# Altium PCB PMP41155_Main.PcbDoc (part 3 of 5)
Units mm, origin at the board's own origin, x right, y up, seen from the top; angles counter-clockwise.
Board outline 74 x 146.5 mm, 8 copper layers (Top Layer, Signal Layer 1, Signal Layer 2, Signal Layer 3, Signal Layer 4, Signal Layer 5, Signal Layer 6, Bottom Layer), stack 1.534 mm thick; 249 components, 190 nets, 902 pads, 747 vias.
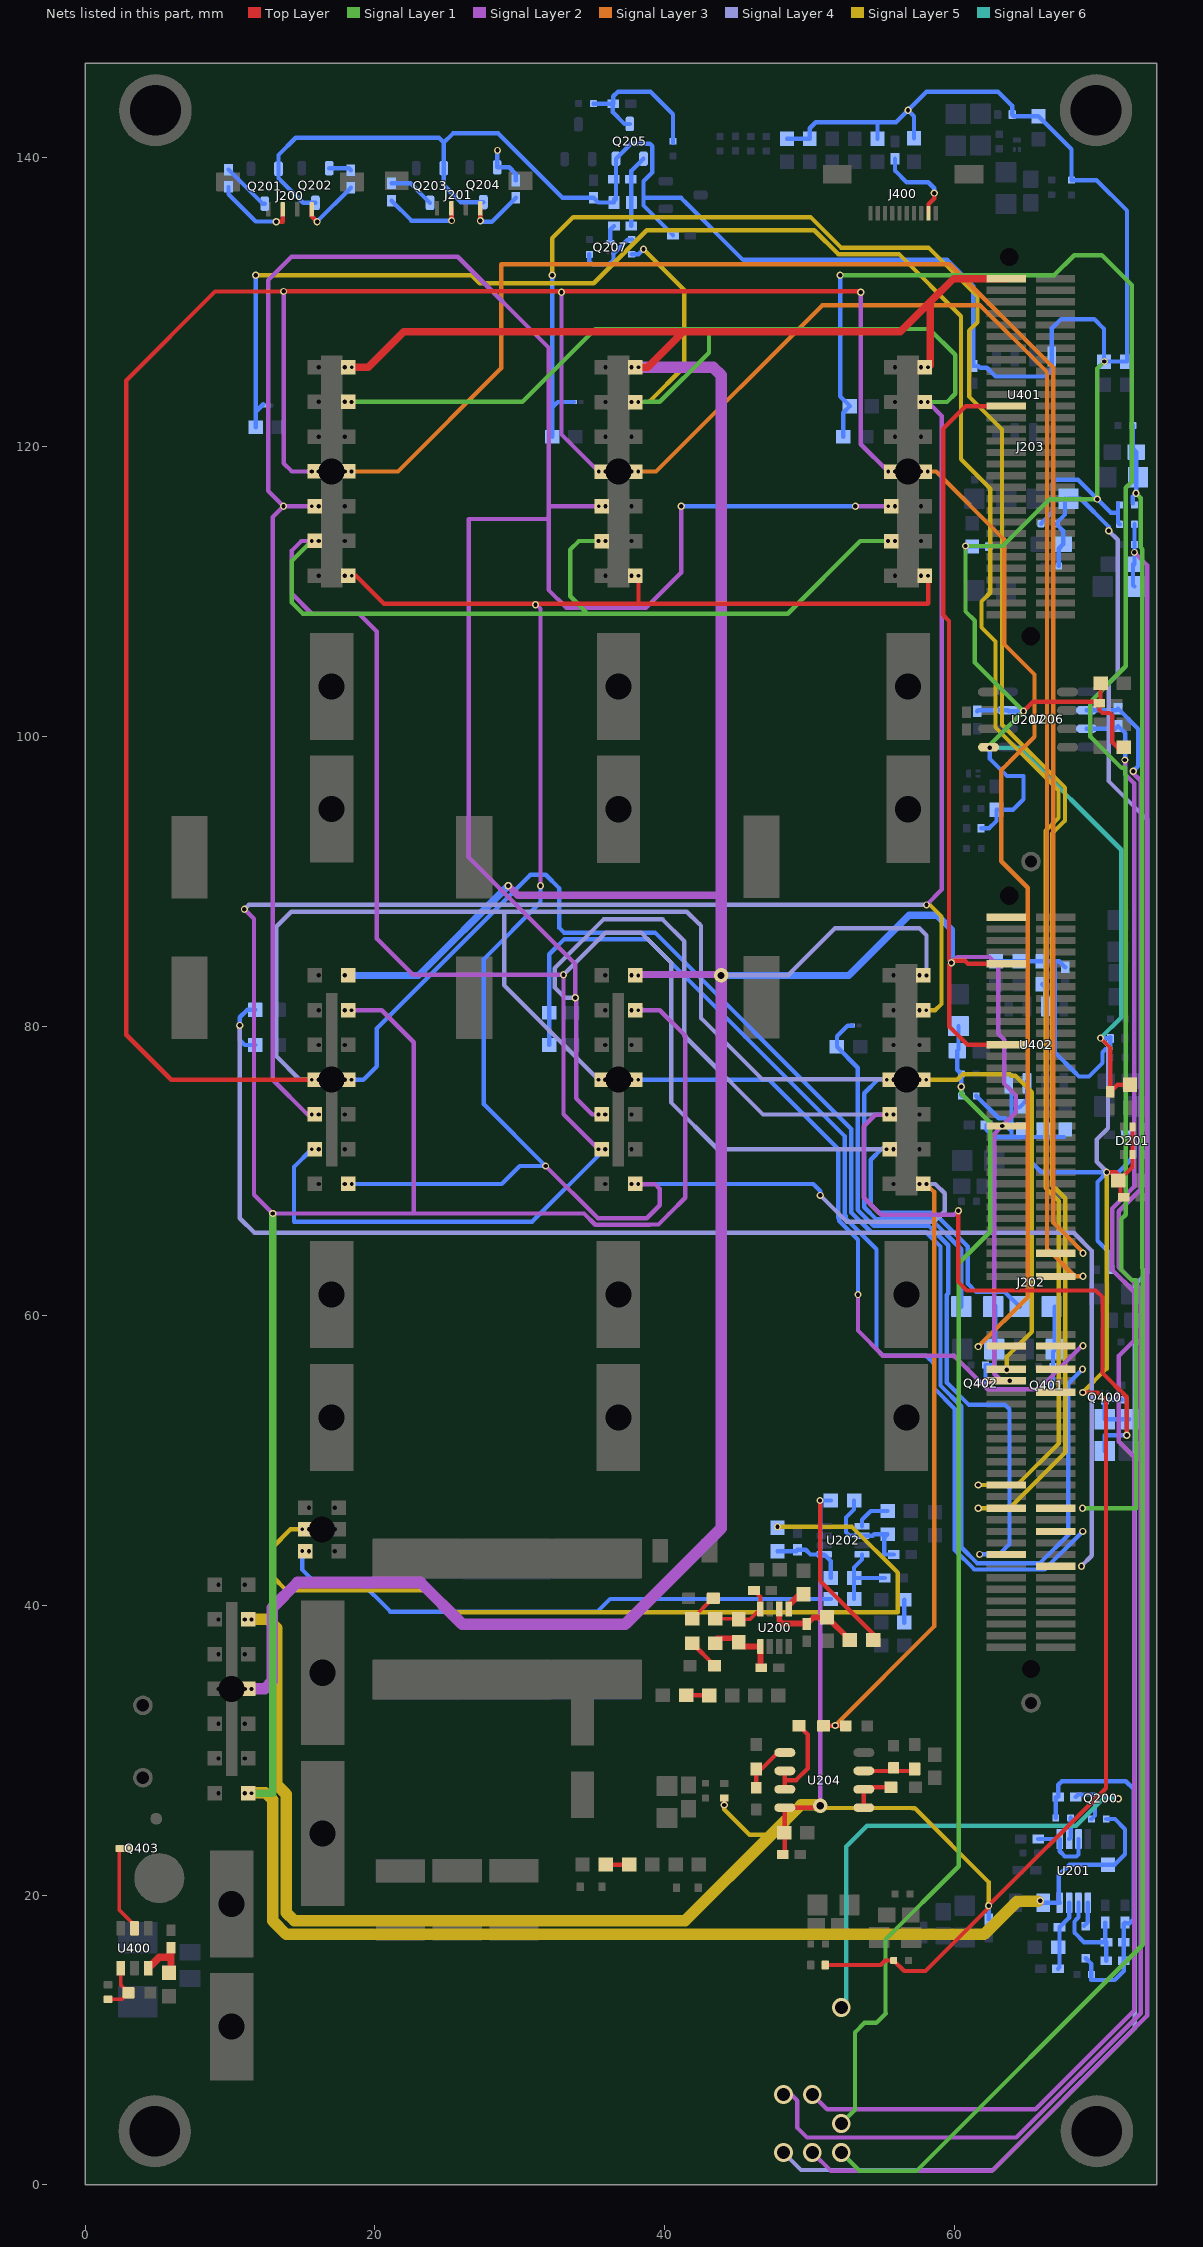
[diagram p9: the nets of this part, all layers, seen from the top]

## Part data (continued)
R243: library part CMP-0031931-1, "0 Ohms Jumper Chip Resistor 0603 (1608 Metric) Metal Element", Digikey Part Number=541-3927-1-ND, Manufacturer=Vishay, Mouser Part Number=71-WSL060300000ZEA9, Operating Temperature Range="-65°C to +170°C", TempCo=3900ppm/°C
R244: library part CMP-0026408-2, "RES, 4.32 k, 1%, 0.063 W, AEC-Q200 Grade 0, 0402", Manufacturer=Vishay-Dale, Power_W=63mW, Supplier Part Number 1=541-4.32KLCT-ND, TempCo="100 ppm/C", Tolerance_%=1%, Value2=0.063W, Value_Code=4k32, ValueDisplayed=4.32k
R249 R255: library part CMP-0026918-5, "RES, 3.3 k, 5%, 0.063 W, AEC-Q200 Grade 0, 0402", Manufacturer=Vishay-Dale, Power_W=63mW, Supplier Part Number 1=541-3.3KJCT-ND, TempCo="200 ppm/C", Tolerance_%=5%, Value2=0.063W, Value_Code=3k30, ValueDisplayed=3.3k
R250 R258 R265 R408 R422 R437 R451: library part CMP-0094182-1, "100 kOhms ±5% 0.063W, 1/16W Chip Resistor 0402 (1005 Metric) Moisture Resistant Thick Film", Digikey Part Number=311-100KJRCT-ND, Manufacturer=YAGEO, Mouser Part Number=603-RC0402JR-07100KL, Operating Temperature Range="-55°C to +155°C", Power_W=63mW, TempCo=100ppm/°C, Tolerance_%=5%
R251 R252 R254 R259 R262 R263 R266 R412 R413 R428 R429 R433 R434 R435 R436 R446 R447 R448 R449: library part CMP-0023152-5, "RES, 4.75 k, 1%, 0.1 W, 0603", Manufacturer=Yageo, Power_W=100mW, Supplier Part Number 1=311-4.75KHRCT-ND, TempCo="100 ppm/C", Tolerance_%=1%, Value2=0.1W, Value_Code=4k75, ValueDisplayed=4.75k
R253 R256: library part CMP-0121543-1, "0 Ohms Jumper Chip Resistor 0402 (1005 Metric) Automotive AEC-Q200 Thick Film", Digikey Part Number=10-ERJ-H2G0R00XCT-ND, Manufacturer=Panasonic, Mouser Part Number=667-ERJ-H2G0R00X, Operating Temperature Range="-55°C to +175°C"
R257 R264: library part CMP-0026833-3, "RES, 120, 5%, 0.063 W, AEC-Q200 Grade 0, 0402", Manufacturer=Vishay-Dale, Power_W=63mW, Supplier Part Number 1=541-120JCT-ND, TempCo="200 ppm/C", Tolerance_%=5%, Value2=0.063W, Value_Code=120R, ValueDisplayed=120
R260 R261 R268 R269 R400 R401 R402 R403 R404 R405 R414 R415 R416 R417 R425 R426 R427 R440 R441 R442 R453 R454 R455: library part CMP-0096818-1, "0 Ohms Jumper 0.245W Chip Resistor 0805 (2012 Metric) - Metal Element", Digikey Part Number=JR0805X35ECT-ND, Manufacturer=Ohmite, Mouser Part Number=588-JR0805X35E, Operating Temperature Range="-55°C to +150°C", Power_W=245mW
R267: library part CMP-0022745-5, "RES, 10.7 k, 1%, 0.1 W, 0603", Manufacturer=Yageo, Power_W=100mW, Supplier Part Number 1=311-10.7KHRCT-ND, TempCo="100 ppm/C", Tolerance_%=1%, Value2=0.1W, Value_Code=10k7, ValueDisplayed=10.7k
R300 R301 R302 R303 R304 R305: library part CMP-0096319-1, "400 µOhms ±1% 9W Chip Resistor Nonstandard Automotive AEC-Q200, Current Sense, Moisture Resistant Metal Element", Digikey Part Number=YAG6132CT-ND, Manufacturer=YAGEO, Mouser Part Number=603-PU3921FKNP90U4L, Operating Temperature Range="-65°C to +170°C", Power_W=9W, TempCo=175ppm/°C, Tolerance_%=1%
R406: library part CMP-0094733-1, "100Ω ±1% 0.063W 0402 Thick Film Chip Resistor AEC-Q200 compliant", Manufacturer="Stackpole Electronics", Operating Temperature Range="-55°C to +155°C", Power_W=63mW, TempCo=100ppm/°C, Tolerance_%=1%
R407: library part CMP-0026716-1, "RES, 1.00 k, 1%, 0.063 W, 0402", Manufacturer=Rohm, Power_W=63mW, Supplier Part Number 1=RHM1.00KLCT-ND, TempCo="100 ppm/C", Tolerance_%=1%, Value2=0.063W, Value_Code=1k00, ValueDisplayed=1.00k
R411 R438 R450: library part CMP-0026996-2, "RES, 20 k, 5%, 0.1 W, AEC-Q200 Grade 0, 0402", Manufacturer=Panasonic, Power_W=100mW, Supplier Part Number 1=P20KJCT-ND, TempCo="200 ppm/C", Tolerance_%=5%, Value2=0.1W, Value_Code=20k0, ValueDisplayed=20k
RT400: library part CMP-0002562-3, "Thermistor NTC, 50 ohm, 25%, D12.5xH16.5mm", Manufacturer=TDK, Supplier Part Number 1=495-3880-ND, Tolerance_%=25%
U200: library part CMP-0093655-2, "-4-V to 110-V, Bidirectional, 1-MHz, 5V/μs, Ultra-Precise Current Sense Amplifier, SOT23-8", Input Bias Current=40uA, Input Offset Voltage=0.002mV, Manufacturer="Texas Instruments", Max Supply Voltage=20V, Min Supply Voltage=2.7V, Nominal Supply Current=2.5mA, Operating Temperature Range="-40°C to +125°C", Voltage Gain=0.1V/mV
U201: library part CMP-0124506-1, "Automotive, High-Voltage, Precision, Rail-to-Rail In, Rail-to-Rail Out Op Amp", Input Bias Current=5pA, Input Offset Voltage=5uV, Manufacturer="Texas Instruments", Max Dual Supply Voltage=18V, Max Supply Voltage=36V, Min Dual Supply Voltage=2.25V, Min Supply Voltage=4.5V, Nominal Supply Current=1mA, Operating Temperature Range="-40°C to +125°C", Output Current Per Channel=65mA, Voltage Gain=140dB
U202: library part CMP-0093654-2, "-4-V to 110-V, Bidirectional, 1-MHz, 5V/μs, Ultra-Precise Current Sense Amplifier, SOT23-8", Input Bias Current=40uA, Input Offset Voltage=0.002mV, Manufacturer="Texas Instruments", Max Supply Voltage=20V, Min Supply Voltage=2.7V, Nominal Supply Current=2.5mA, Operating Temperature Range="-40°C to +125°C", Voltage Gain=0.05V/mV
U204: library part CMP-0013007-4, "10-MHz, Low-Noise, RRIO, CMOS Operational Amplifier for Cost-Sensitive Systems, D0008A (SOIC-8)", Alternate Manufacturer="Texas Instruments", Alternate PartNumber=TLV9062ID, Operating Temperature Range="-40 to 125 C", Rating=Catalog
U206: library part CMP-0033354-1, "3.3V CAN Transceiver with Sleep Mode, 6 mA, -40 to 125 degC, 8-pin SOIC (D), Green (RoHS & no Sb/Br)", Bus Fault Voltage(V)=+/-30, Drivers Per Package=1, Low Power Mode=Sleep, Manufacturer="Texas Instruments", Rating=Catalog, Supply Voltage(s)(V)=3.3
U207: library part CMP-0029827-1, "3.3 V Supply RS-485 with IEC ESD Protection, 20 Mbps, -40 to 125 degC, 8-Pin SOIC, RoHS, Tape and Reel", Manufacturer="Texas Instruments", Operating Temperature Range="-40 to 125 degC"
U400: library part CMP-0066129-2, "High Side OR-ing FET Controller, DDC0006A (SOT-23-T-6)", Alternate Manufacturer="Texas Instruments"
U401 U402: library part CMP-0086585-1, "IC EEPROM 1M I2C 1MHZ 8SO", Manufacturer="ST Microelectronics"

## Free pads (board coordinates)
  round 5 hole 3.5: 1(4.8,3.7) 1(4.85,143.25) 1(69.8,143.25) 1(69.86,3.7)
  rect 1x1 hole 0.3 copper offset -0.254,0: 1(9.21,27.04) 1(9.21,29.44) 1(9.21,31.84) 1(9.21,34.24) 1(9.21,36.64) 1(9.21,39.04) 1(9.21,41.44) 1(15.46,45.26) 1(15.46,46.76) 1(15.46,43.76) 1(16.12,69.11) 1(16.12,71.51) 1(16.12,73.91) 1(16.12,76.31) 1(16.12,78.71) 1(16.12,81.11) 1(16.12,83.51) 1(16.12,111.11) 1(16.12,113.51) 1(16.12,115.91) 1(16.12,118.31) 1(16.12,120.71) 1(16.12,123.11) 1(16.12,125.51) 1(35.92,69.11) 1(35.92,71.51) 1(35.92,73.91) 1(35.92,76.31) 1(35.92,78.71) 1(35.92,81.11) 1(35.92,83.51) 1(35.924,111.103) 1(35.924,113.503) 1(35.924,115.903) 1(35.924,118.303) 1(35.924,120.703) 1(35.924,123.103) 1(35.924,125.503) 1(55.81,69.11) 1(55.81,71.51) 1(55.81,73.91) 1(55.81,76.31) 1(55.81,78.71) 1(55.81,81.11) 1(55.81,83.51) 1(55.918,111.105) 1(55.918,113.505) 1(55.918,115.905) 1(55.918,118.305) 1(55.918,120.705) 1(55.918,123.105) 1(55.918,125.505)
  rect 1x1 hole 0.3 copper offset 0.254,0: 1(11.01,27.04) 1(11.01,29.44) 1(11.01,31.84) 1(11.01,34.24) 1(11.01,36.64) 1(11.01,39.04) 1(11.01,41.44) 1(17.24,46.76) 1(17.24,43.76) 1(17.24,45.26) 1(17.92,69.11) 1(17.92,71.51) 1(17.92,73.91) 1(17.92,76.31) 1(17.92,78.71) 1(17.92,81.11) 1(17.92,83.51) 1(17.92,111.11) 1(17.92,113.51) 1(17.92,115.91) 1(17.92,118.31) 1(17.92,120.71) 1(17.92,123.11) 1(17.92,125.51) 1(37.72,69.11) 1(37.72,71.51) 1(37.72,73.91) 1(37.72,76.31) 1(37.72,78.71) 1(37.72,81.11) 1(37.72,83.51) 1(37.724,111.103) 1(37.724,113.503) 1(37.724,115.903) 1(37.724,118.303) 1(37.724,120.703) 1(37.724,123.103) 1(37.724,125.503) 1(57.61,69.11) 1(57.61,71.51) 1(57.61,73.91) 1(57.61,76.31) 1(57.61,78.71) 1(57.61,81.11) 1(57.61,83.51) 1(57.718,111.105) 1(57.718,113.505) 1(57.718,115.905) 1(57.718,118.305) 1(57.718,120.705) 1(57.718,123.105) 1(57.718,125.505)
  rect 3x7.4 hole 1.8 square: 2(10.11,10.92) 2(17.02,52.99) 2(17.02,94.99) 2(36.82,52.99) 2(36.824,94.983) 2(56.71,52.99) 2(56.818,94.985)
  rect 3x7.4 hole 1.8 square unplated: 2(10.11,19.4) 2(17.02,61.47) 2(17.02,103.47) 2(36.82,61.47) 2(36.824,103.463) 2(56.71,61.47) 2(56.818,103.465)
  rect 0.8x12 hole 1.8 square unplated: 2(10.11,34.24) 2(17.02,76.31) 2(36.82,76.31)
  rect 0.8x1.6 hole 1.8 square unplated: 2(16.35,45.26)
  rect 3x10 hole 1.8 square: 2(16.4,24.25) 2(16.4,35.36)
  rect 1.5x16 hole 1.8 square: 2(17.02,118.31) 2(36.824,118.303) 2(56.71,76.31) 2(56.818,118.305)

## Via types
v1: diameter 0.5, hole 0.3, Top Layer to Bottom Layer, 533 vias
v2: diameter 0.508, hole 0.254, Top Layer to Bottom Layer, tented both sides, 102 vias
v3: diameter 1.5, hole 1.2, Top Layer to Bottom Layer, 72 vias
v4: diameter 1.3, hole 0.9, Top Layer to Bottom Layer, 30 vias
v5: diameter 1.27, hole 0.711, Top Layer to Bottom Layer, 6 vias
v6: diameter 1, hole 0.5, Top Layer to Bottom Layer, 2 vias
v7: diameter 2.49, hole 2.49, Top Layer to Bottom Layer, 2 vias

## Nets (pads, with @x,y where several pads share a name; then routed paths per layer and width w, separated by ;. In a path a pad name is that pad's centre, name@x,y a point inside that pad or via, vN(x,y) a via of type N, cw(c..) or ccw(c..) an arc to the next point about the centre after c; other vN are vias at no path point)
3V3: C217.1 C218.1 C222.2 C231.1 C233.1 C406.1 C411.1 D201.2 D201.5 J202.45 pad.1@11.01,39.04 Q201.2 Q202.3 Q203.2 Q204.3 Q205.2 R203.1 R210.1 R236.2 R241.2 R248.2 R249.1 R250.2 R251.2 R252.2 R254.2 R255.1 R258.2 R259.2 R262.2 R263.2 R265.2 R266.2 R408.2 R409.2 R410.2 R411.2 R412.2 R413.2 R422.2 R423.2 R424.2 R428.2 R429.2 R433.2 R434.2 R435.2 R436.2 R437.2 R438.2 R439.2 R446.2 R447.2 R448.2 R449.2 R450.2 R451.2 R452.2 U204.8 U206.3 U207.8 U401.8 U402.8 | length 504.7
  Top Layer w0.3: v1(44.13,26.23) 44.13,26.699 R422.2@44.139,26.708 ; C218.1@48.17,22.804 48.315,22.949 C217.1@48.315,24.314 ; C217.1@48.26,24.314 C217.1@48.26,24.569 ; C217.1@48.315,24.569 U204.8@48.315,26.039 50.621,26.039 v6(50.764,26.182) ; v1(50.738,47.253) 50.738,41.712 54.41,38.04 R203.1@54.41,37.615 ; R408.2@51.101,15.181 54.941,15.181 55.251,15.491 R452.2@55.823,15.491 56.554,14.76 58.025,14.76 62.381,19.117 v1(62.381,19.278) 70.483,27.38 70.483,54.134 69.907,54.71 v1(68.88,54.71) ; v1(64.79,101.75) 65.444,102.404 69.926,102.404 C233.1@70.03,102.3 ; v1(70.11,79.18) 70.791,78.499 R255.1@70.791,75.468 71.283,75.96 R254.2@72.14,75.96 ; R262.2@70.11,103.69 70.11,102.38 C233.1@70.03,102.3 ; v1(70.53,69.92) 71.175,69.92 71.33,69.765 R252.2@71.33,69.34 71.487,69.183 71.487,68.423 R249.1@71.72,68.19 ; R252.2@71.38,69.34 72.32,70.28 D201.5@72.32,71.14 D201.2@72.32,73.04 ; R263.2@71.722,99.257 71.283,99.257 70.922,99.618 70.922,100.948 70.919,100.951 70.919,101.455 70.745,101.629 70.241,101.629 70.03,101.84 C233.1@70.03,102.3
  Signal Layer 2 w0.3: v1(50.738,47.253) 50.764,47.227 v6(50.764,26.182)
  Signal Layer 1 w0.3: v1(62.473,99.218) 62.473,99.433 v1(64.79,101.75) 61.419,105.121 61.419,108.011 60.784,108.646 v1(60.784,113.159) 63.364,113.159 66.605,116.4 v1(69.89,116.4) 69.89,125.413 v1(70.377,125.9)
  Signal Layer 4 w0.3: v1(70.11,79.18) 70.622,78.668 70.622,72.955 69.849,72.183 69.849,70.651 v1@70.58,69.92
  Signal Layer 5 w0.3: v1(44.13,26.23) 44.13,25.914 45.874,24.17 47.366,24.17 ; v6(50.764,26.182) 50.927,26.02 57.106,26.02 57.113,26.013 57.279,26.013 62.381,20.91 v1(62.381,19.278) ; v1(68.88,54.71) 70.53,56.36 v1(70.53,69.92)
  Signal Layer 5 w0.8: pad.1@11.566,39.04 12.65,39.04 13.24,38.45 13.24,27.624 13.887,26.977 13.887,18.794 14.434,18.247 41.443,18.247 47.366,24.17 49.426,26.23 50.764,26.23 v6(50.764,26.182)
  Signal Layer 6 w0.3: v1(62.473,99.218) 64.512,99.218 71.54,92.19 71.54,80.61 v1(70.11,79.18)
  Bottom Layer w0.3: Q202.3@15.9,136.855 15.053,136.855 13.347,138.561 Q201.2@13.347,139.201 13.347,140.157 14.54,141.35 24.434,141.35 24.763,141.021 ; Q204.3@27.498,136.908 25.932,136.908 24.763,138.077 Q203.2@24.763,139.253 24.763,141.021 ; C222.2@36.517,137.097 C222.2@36.517,136.877 35.435,136.877 R241.2@35.1,137.212 32.958,137.212 28.518,141.652 25.395,141.652 24.763,141.021 ; C222.2@36.652,137.097 Q205.2@36.652,139.902 37.687,140.938 38.985,140.938 39.149,140.773 39.149,138.948 38.552,138.351 38.552,137.198 ; R248.2@40.59,134.63 38.552,136.668 38.552,137.198 ; R446.2@48.465,141.28 R447.2@50.025,141.28 50.025,142.003 50.442,142.42 54.705,142.42 ; v1(50.738,47.253) R210.1@51.488,47.253 ; R448.2@54.705,141.29 54.705,142.42 ; R449.2@57.23,141.31 57.23,142.838 v1(56.818,143.25) ; v1(60.784,113.159) 60.816,113.126 R259.2@61.259,113.126 R258.2@62.575,113.126 ; R410.2@61.533,75.19 63.078,73.644 63.089,73.654 63.542,73.654 63.863,73.334 63.863,72.88 63.852,72.87 63.968,72.755 ; C231.1@61.59,101.755 61.655,101.82 U206.3@63.695,101.82 63.765,101.75 v1(64.79,101.75) ; R250.2@61.865,93.665 62.418,93.665 62.926,94.173 R251.2@62.926,94.955 64.067,94.955 64.79,95.678 64.79,97.283 63.651,97.283 62.473,98.461 v1(62.473,99.218) ; R438.2@62.237,73.18 62.237,72.84 62.733,72.344 63.315,72.344 63.322,72.338 63.968,72.338 ; R450.2@62.381,18.32 v1(62.381,19.278) ; R429.2@62.885,84.495 R436.2@64.508,84.495 R435.2@66.082,84.495 66.97,84.495 ; U402.8@63.695,75.815 63.968,75.543 63.968,72.755 ; 64.528,72.338 63.968,72.338 ; 64.528,72.355 65.334,72.355 ; R439.2@66.008,114.706 66.8,115.498 66.8,117.52 67.02,117.74 68.55,117.74 v1(69.89,116.4) 70.821,115.469 71.317,115.469 ; 67.593,72.355 65.334,72.355 ; C411.1@67.681,84.065 67.251,84.495 66.97,84.495 ; v1(70.11,79.18) 70.13,79.16 70.693,79.16 70.79,79.257 R437.2@70.79,79.16 70.79,78.406 70.454,78.406 70.251,78.203 70.251,77.468 69.315,76.533 68.623,76.533 68.303,76.853 66.97,78.186 66.97,84.495 ; R451.2@70.83,63.185 70.647,63.368 70.647,64.445 69.9,65.193 69.9,69.24 v1@70.58,69.92 ; R409.2@71.317,116.094 71.317,115.469 ; R423.2@71.427,114.658 71.317,114.768 71.317,115.469 ; R411.2@71.916,72.503 72.478,71.941 72.478,71.056 71.342,69.92 v1@70.58,69.92 ; 38.552,137.198 41.149,137.198 41.548,136.799 45.43,132.917 59.53,132.917 61.328,131.119 C406.1@61.328,125.59 61.686,125.59 61.803,125.473 62.253,125.473 62.855,124.87 66.29,124.87 66.736,125.316 U401.8@66.736,126.24 66.736,128.179 67.386,128.83 69.673,128.83 70.35,128.153 R412.2@70.35,125.9 R413.2@71.94,125.9 71.94,136.32 69.837,138.423 R424.2@68.11,138.423 68.11,140.55 R266.2@65.82,142.84 64.12,142.84 R265.2@64.01,142.95 64.01,143.55 63.03,144.53 58.098,144.53 v1(56.818,143.25) ; 54.705,142.42 55.988,142.42 v1(56.818,143.25) ; 63.968,72.338 63.968,72.755 ; 65.334,72.355 65.334,70.626 66.04,69.92 v1@70.58,69.92
  other v2: 11.48,39.04
5V: J202.48 J202.84 J202.98 J202.112 J203.158 J203.180 pad.1@11.01,34.24 pad.1@17.92,83.51 pad.1@17.92,125.51 pad.1@37.72,83.51 pad.1@37.724,125.503 pad.1@57.61,83.51 pad.1@57.718,125.505 | length 346.2
  Top Layer w0.3: J202.98@63.6,78.72 60.927,78.72 59.67,79.977 59.67,84.243 v1(59.812,84.385) ; J202.112@63.6,84.32 60.954,84.32 60.747,84.527 59.955,84.527 v1(59.812,84.385) ; J203.158@63.6,122.82 60.81,122.82 59.255,121.266 59.255,108.377 59.65,107.983 59.65,84.547 v1(59.812,84.385)
  Top Layer w0.5: v2(18.4,125.51) 19.55,125.51 21.99,127.95 41.29,127.95 ; v2(38.204,125.503) 38.843,125.503 41.29,127.95 ; pad.1@58.35,125.636 58.35,130.02 ; J203.180@63.6,131.62 59.95,131.62 58.35,130.02 ; 41.29,127.95 56.28,127.95 58.35,130.02
  Signal Layer 2 w0.3: 43.813,89.34 43.91,89.437 ; v1@59.884,84.456 60.207,84.78 62.44,84.78 63.053,84.167 63.053,79.488 63.473,79.067 63.473,76.02 64.273,75.22 64.273,74.064 v1(63.315,73.107) 62.77,72.562 62.77,56.01 63.26,55.52 v1(63.834,55.52)
  Signal Layer 2 w0.5: v1(29.21,89.7) 29.473,89.437 29.477,89.437 29.861,89.053 43.91,89.053 44.08,89.053 ; pad.1@38.2,83.58 v6@43.91,83.58
  Signal Layer 2 w0.8: pad.1@11.566,34.24 12.39,34.24 12.91,34.76 12.91,39.84 14.663,41.593 23.158,41.593 26.035,38.716 37.296,38.716 43.91,45.33 v6(43.91,83.51) 43.91,83.58 43.91,89.053 43.91,89.437 43.91,124.953 43.373,125.49 pad.1@38.275,125.49
  Signal Layer 4 w0.3: v6(43.91,83.51) 48.52,83.51 51.776,86.766 57.61,86.766 58.09,86.286 pad.1@58.09,83.567
  Bottom Layer w0.5: pad.1@18.39,83.51 23.02,83.51 v1(29.21,89.7) ; v6(43.91,83.51) 52.72,83.51 56.88,87.67 58.82,87.67 59.812,86.678 v1(59.812,84.385)
  other v2: 11.48,34.24 38.2,83.51 58.09,83.51 58.198,125.505
12V: C202.1 C203.2 pad.1@11.01,27.04 pad.1@17.92,81.11 pad.1@17.92,123.11 pad.1@37.72,81.11 pad.1@37.724,123.103 pad.1@57.61,81.11 pad.1@57.718,123.105 R207.1 R245.2 U201.4 | length 362.7
  Signal Layer 2 w0.3: v1(10.994,88.084) 11.66,87.419 11.66,68.358 v1(12.948,67.069) 22.689,67.069 ; v2(18.39,81.11) 20.48,81.11 22.689,78.901 22.689,67.069 ; 38.48,81.13 38.5,81.11 39.68,81.11 41.43,79.36 41.43,68.16 40.339,67.069 39.583,66.313 38.982,66.313 38.962,66.293 35.218,66.293 34.442,67.069 22.689,67.069 ; v1(58.091,88.378) 59.15,89.437 59.15,122.143 v2(58.188,123.105)
  Signal Layer 1 w0.3: pad.1@18.602,123.12 18.612,123.11 30.175,123.11 35.215,128.15 43.07,128.15 ; 38.578,123.103 38.595,123.12 39.68,123.12 43.07,126.51 43.07,128.15 ; 58.526,123.105 59.51,123.105 60.075,123.669 60.075,126.36 58.285,128.15 54.724,128.15 54.707,128.133 54.253,128.133 54.236,128.15 43.07,128.15
  Signal Layer 1 w0.5: v2(11.49,27.04) 12.948,27.04 v1(12.948,67.069)
  Signal Layer 4 w0.3: v1(10.994,88.084) 11.288,88.378 v1(58.091,88.378)
  Signal Layer 5 w0.3: v2(38.194,123.103) 38.923,123.103 41.36,125.54 41.36,130.842 v1(38.552,133.65) ; v2(58.08,81.11) 58.679,81.11 58.69,81.099 59.13,81.539 59.13,87.58 58.332,88.378 v1(58.091,88.378)
  Signal Layer 5 w0.8: pad.1@11.565,27.084 12.44,27.084 12.94,26.584 12.94,18.23 13.87,17.3 62.08,17.3 64.37,19.59 v1@65.81,19.59
  Bottom Layer w0.3: R245.2@37.732,133.305 38.207,133.305 v1(38.552,133.65) ; C203.2@66.155,19.475 U201.4@67.289,19.475 67.23,19.534 67.23,21.37 67.965,22.105 C202.1@70.634,22.105 71.085,22.105 71.804,22.825 71.804,24.556 71.105,25.255 R207.1@70.506,25.255
  other v1: 65.942,19.62
  other v2: 38.19,81.11 18.39,123.11
BBU_ADDR0: C408.1 R409.1 R415.2 R419.2 | length 133.8
  Signal Layer 1 w0.3: v4(52.21,2.24) 53.49,0.96 57.407,0.96 73.02,16.573 73.02,62.802 73.02,63.255 72.997,63.278 72.997,112.493 72.997,112.947 72.88,113.064 72.88,116.48 v1(72.56,116.8)
  Bottom Layer w0.3: R409.1@72.342,116.094 72.342,116.582 v1(72.56,116.8) ; R419.2@72.342,121.48 72.342,119.873 C408.1@72.576,119.64 72.576,117.91 72.576,116.8 v1@72.561,116.785
BBU_ADDR1: C413.1 R423.1 R426.2 R431.2 | length 133.9
  Signal Layer 2 w0.3: v4(50.21,2.24) 51.49,0.96 62.62,0.96 73.327,11.667 73.327,111.843 v1(72.45,112.72)
  Signal Layer 1 w0.3: v4@50.21,2.173 v4(50.21,2.24)
  Bottom Layer w0.3: C413.1@72.356,111.897 72.356,111.467 72.356,110.461 R426.2@72.455,110.362 ; C413.1@72.452,111.897 72.452,112.718 v1(72.45,112.72) 72.452,112.722 R423.1@72.452,114.658
BBU_ADDR2: C416.1 R439.1 R441.2 R444.2 | length 143.3
  Signal Layer 4 w0.3: v4(48.21,2.24) 49.429,1.021 62.681,1.021 72.48,10.82 72.48,62.13 73.327,62.977 73.327,64.509 73.327,94.063 73.327,94.282 70.67,96.939 70.67,103.69 71.3,104.32 71.3,113.589 v1(70.67,114.219)
  Bottom Layer w0.3: R444.2@67.223,111.777 67.223,112.977 C416.1@67.536,113.29 67.536,114.202 R439.1@67.033,114.706 67.66,115.333 R441.2@67.66,116.42 ; R441.2@67.9,116.42 68.75,116.42 70.67,114.5 v1(70.67,114.219)
BBU_ISHARE: Q200.3 | length 32.3
  Signal Layer 6 w0.3: v4(52.21,12.24) 52.559,12.589 52.559,23.362 53.991,24.794 68.42,24.794 70.286,26.66 v1(71.33,26.66)
  Bottom Layer w0.3: Q200.3@70.435,26.69 71.3,26.69 v1(71.33,26.66)
CAN_H: R257.2 U206.7 | length 119
  Signal Layer 2 w0.3: v4(50.21,6.24) 51.24,5.21 65.605,5.21 67.312,6.917 72.433,12.038 72.433,50.26 71.378,51.315 71.378,51.992 71.378,54.923 71.367,54.933 71.367,55.387 71.369,55.388 71.369,56.532 71.369,57.236 72.433,58.3 72.433,61.662 70.92,63.175 70.92,67.415 71.2,67.695 72.433,68.928 72.433,96.771 71.815,97.388 71.815,98.361 v1(71.792,98.385)
  Bottom Layer w0.3: U206.7@69.145,100.55 71.135,100.55 R257.2@71.317,100.732 71.81,100.239 71.81,98.385 v1(71.792,98.385)
CAN_L: R257.1 U206.6 | length 125.1
  Signal Layer 2 w0.3: v4(48.21,6.24) 48.75,6.24 49.18,5.81 49.18,3.93 49.84,3.27 64.297,3.27 72.88,11.853 72.88,61.847 71.367,63.36 71.367,67.23 72.88,68.743 72.88,96.956 72.292,97.544 v1(72.363,97.615)
  Bottom Layer w0.3: U206.6@69.145,101.82 71.205,101.82 R257.1@71.317,101.932 72.7,100.549 72.7,97.952 v1(72.363,97.615)
COMP: C221.2 pad.1@17.92,69.11 pad.1@17.92,111.11 pad.1@37.72,69.11 pad.1@37.724,111.103 pad.1@57.61,69.11 pad.1@57.718,111.105 R233.1 | length 179.7
  Top Layer w0.3: v2(18.4,111.11) 18.7,111.11 20.63,109.18 38.204,109.18 ; pad.1@38.204,110.739 38.204,109.18 ; R233.1@50.99,31.694 51.704,31.694 51.73,31.72 51.756,31.694 v1@51.787,31.694 ; v1(51.787,31.72) v1@51.787,31.694 ; C221.2@52.51,31.694 v1@51.787,31.694 ; pad.1@58.21,111.105 58.21,109.202 58.188,109.18 38.204,109.18
  Signal Layer 2 w0.3: v1@31.1,109.18 31.443,108.837 v1(31.443,89.7) ; v1(31.791,70.353) 35.404,66.74 38.776,66.74 39.68,67.644 39.68,68.77 39.35,69.1 38.49,69.1 38.48,69.11
  Signal Layer 3 w0.3: v1(51.787,31.72) 58.618,38.551 58.618,68.563 pad.1@58.091,69.09
  Signal Layer 4 w0.3: v1(50.764,68.32) 52.595,66.489 58.618,66.489 59.35,67.221 59.35,68.464 58.704,69.11 58.381,69.11
  Bottom Layer w0.3: v2(18.4,69.11) 28.77,69.11 30.013,70.353 v1(31.791,70.353) 27.53,74.614 27.53,84.644 31.443,88.557 v1(31.443,89.7) ; v2(38.2,69.11) 50.268,69.11 50.764,68.613 v1(50.764,68.32)
  other v1: 31.092,109.109
  other v2: 58.09,69.11 38.204,111.103 58.198,111.105
COMP_DIR: pad.1@16.12,73.91 pad.1@16.12,115.91 pad.1@35.92,73.91 pad.1@35.924,115.903 pad.1@55.81,73.91 pad.1@55.918,115.905 R400.2 | length 263.2
  Top Layer w0.3: v1@60.295,67.259 60.295,62.335 60.874,61.756 69.784,61.756 70.242,61.298 70.242,56.059 71.925,54.375 v1(71.925,51.765)
  Signal Layer 2 w0.3: v2(15.65,73.91) 15.348,73.91 12.948,76.31 12.948,115.161 v1(13.697,115.91) ; v2(15.65,115.91) v1(13.697,115.91) ; 33.23,108.9 38.73,108.9 41.153,111.323 v1(41.153,115.91) ; 33.229,108.901 32,110.13 32,115.03 32,115.161 ; v1(33.839,81.971) 33.839,83.461 33.839,84.301 29.25,88.89 29.246,88.89 28.663,89.473 28.663,89.477 26.49,91.65 26.49,94.044 26.49,115.03 31.869,115.03 32,115.161 ; v1@33.9,82 33.9,75.03 35.02,73.91 v2(35.45,73.91) ; v2(35.454,115.903) 32,115.903 ; v1(53.185,115.903) 53.187,115.905 v2(55.448,115.905) ; 55.05,73.89 54.55,73.89 53.76,73.1 53.76,68.178 54.958,66.98 60.011,66.98 v1(60.295,67.264) ; v1(13.697,115.91) 12.64,116.967 12.64,131.522 14.248,133.13 25.73,133.13 32,126.86 32,115.903 ; 32,115.161 32,115.903
  Signal Layer 4 w0.3: v1(33.839,81.971) 33.127,81.971 32.425,82.674 32.425,84.015 35.79,87.38 39.87,87.38 41.369,85.88 41.369,79.341 46.8,73.91 v2(55.34,73.91)
  Bottom Layer w0.3: v1(41.153,115.91) 41.16,115.903 v1(53.185,115.903) ; R400.2@70.405,50.665 70.405,51.765 v1(71.925,51.765)
CS+_total_charge_current_battery: pad.1@15.46,43.76 R211.2 | length 39.3
  Bottom Layer w0.3: v2(14.98,43.76) 14.98,42.49 15.7,41.77 18.883,41.77 21.073,39.58 35.378,39.58 36.248,40.45 R211.2@51.488,40.45
CS+_total_discharge_current_bus: R204.2 R306.1 | length 2
  Top Layer w0.254: R204.2@41.91,39.09 43.313,40.493 R306.1@43.37,40.493
CS-_total_charge_current_battery: pad.1@15.46,45.26 R213.2 | length 61.1
  Signal Layer 5 w0.3: v2(14.98,45.26) 14.18,45.26 12.95,44.03 12.95,41.99 13.897,41.043 23.644,41.043 25.147,39.54 56.12,39.54 56.12,42.263 52.951,45.432 v1(47.804,45.432)
CS-_total_discharge_current_bus: R206.2 R307.1 | length 2.2
  Top Layer w0.254: R206.2@41.91,37.39 R206.2@41.92,37.39
  Top Layer w0.3: R206.2@41.92,37.39 R307.1@43.46,35.85
FB_DIR: pad.1@16.12,71.51 pad.1@16.12,113.51 pad.1@35.92,71.51 pad.1@35.924,113.503 pad.1@55.81,71.51 pad.1@55.918,113.505 R402.2 | length 198
  Signal Layer 2 w0.3: v2(15.64,113.51) 14.93,113.51 14.272,112.852 14.272,109.868 15.65,108.49 18.9,108.49 20.13,107.26 20.13,86.05 22.629,83.551 v1(33.032,83.551) 33.032,73.918 v2(35.44,71.51)
  Signal Layer 1 w0.3: v2(15.64,113.51) 14.265,112.135 14.265,109.256 15.031,108.49 34.687,108.49 ; v2(35.444,113.503) 35.437,113.51 34.09,113.51 33.49,112.91 33.49,109.687 34.687,108.49 ; v2(55.438,113.505) 53.525,113.505 48.51,108.49 34.687,108.49
  Signal Layer 4 w0.3: v1(33.032,83.551) 35.946,86.465 38.387,86.465 40.46,84.393 40.46,74.73 43.68,71.51 54.97,71.51
  Bottom Layer w0.3: v2(15.64,71.51) 14.42,70.29 14.42,66.5 30.859,66.5 35.44,71.081 v2(35.44,71.51) ; 55.02,71.56 54.246,70.786 54.246,67.691 54.828,67.11 58.63,67.11 60.947,64.793 60.947,62.228 61.518,61.657 63.494,61.657 64.512,60.64 R402.2@64.53,60.64
  other v2: 55.33,71.51
MCU_RESET: J202.120
MODE: pad.1@16.12,76.31 pad.1@16.12,118.31 pad.1@35.92,76.31 pad.1@35.924,118.303 pad.1@55.81,76.31 pad.1@55.918,118.305 R404.2 | length 252.2
  Top Layer w0.3: v1@13.666,130.73 8.97,130.73 2.83,124.59 2.83,79.42 5.94,76.31 v2(15.65,76.31) ; v1(13.7,130.74) 53.5,130.74 v1(53.56,130.68)
  Signal Layer 2 w0.3: v1(13.7,130.74) 13.7,118.875 14.272,118.303 v1(15.65,118.303) ; v1(32.89,130.68) 32.89,120.867 v2(35.454,118.303) ; v1(53.56,130.68) 53.56,120.193 v2(55.448,118.305)
  Signal Layer 4 w0.3: v2(15.65,76.31) 14.816,76.31 13.19,77.936 13.19,86.87 14.23,87.91 28.94,87.91 ; v2(35.45,76.31) 28.94,82.82 28.94,87.91 ; pad.1@55.34,76.35 46.732,76.35 42.52,80.562 42.52,86.95 42.4,87.07 42.38,87.07 41.54,87.91 28.94,87.91
  Bottom Layer w0.3: pad.1@55.146,76.35 54.781,76.35 53.799,75.368 53.799,67.85 53.799,67.506 54.642,66.663 54.986,66.663 58.445,66.663 60.5,64.607 R404.2@60.5,60.64
  other v2: 55.34,76.31
NetC200_1: C200.1 C209.2 D200.1 R201.2 R202.2 R214.2 R216.2 | length 25.1
  Bottom Layer w0.3: R214.2@67.021,25.335 R202.2@67.021,26.775 ; R202.2@67.194,26.775 67.194,27.623 67.441,27.87 71.857,27.87 72.402,27.325 72.402,19.835 72.402,19.44 72.402,18.789 72.402,18.352 72.11,18.06 71.857,18.06 R216.2@71.804,18.112 71.709,18.017 71.709,16.752 C200.1@71.709,15.475 71.709,14.759 71.095,14.145 69.481,14.145 69.481,15.255 D200.1@69.084,15.652
NetC200_2: C200.2 R200.2 R201.1 U201.2 | length 7.3
  Bottom Layer w0.3: U201.2@68.589,19.475 68.589,18.472 68.386,18.269 68.386,18.253 68.309,18.175 68.309,17.417 68.974,16.752 R201.1@70.524,16.752 ; R200.2@70.444,18.112 70.444,16.832 R201.1@70.509,16.767 ; C200.2@70.509,15.475 R201.1@70.509,16.752
NetC201_1: C201.1 C204.1 R204.1 U200.8 | length 4.9
  Top Layer w0.254: R204.1@43.51,39.09 45.092,39.09 C201.1@45.131,39.05 45.91,39.05 U200.8@46.628,39.768 46.628,40.597 C204.1@46.182,41.043
NetC201_2: C201.2 C205.1 R206.1 U200.1 | length 4.6
  Top Layer w0.406: R206.1@43.63,37.742 44.839,37.742 C201.2@45.131,37.45 45.414,37.168 U200.1@46.628,37.168 C205.1@46.628,35.76
NetC206_1: C206.1 C207.1 R203.2 U200.6 | length 6.2
  Top Layer w0.406: U200.6@47.928,39.768 47.928,38.973 48.143,38.758 49.449,38.758 ; C207.1@49.83,38.723 50.284,39.177 C206.1@51.221,39.177 51.248,39.177 R203.2@52.81,37.615
NetC210_1: C210.1 R208.2 R209.2 U201.3 | length 4.9
  Bottom Layer w0.3: R208.2@67.174,14.925 67.279,15.031 C210.1@67.279,17.779 67.939,18.438 U201.3@67.939,19.475
NetC211_1: C211.1 C212.1 R211.1 U202.8 | length 5.4
  Bottom Layer w0.3: R211.1@53.088,40.45 C211.1@53.088,41.903 53.088,42.627 53.638,43.177 U202.8@53.638,43.528 ; C211.1@53.089,41.904 C212.1@55.205,41.904
NetC211_2: C211.2 C213.1 R213.1 U202.1 | length 5.2
  Bottom Layer w0.3: R213.1@47.81,43.76 49.095,43.76 C213.1@49.188,43.853 49.763,43.853 50.088,43.528 U202.1@51.038,43.528 51.488,43.078 C211.2@51.488,41.903
NetC214_1: C214.1 C215.1 R210.2 U202.6 | length 7.6
  Bottom Layer w0.3: R210.2@53.088,47.253 53.088,46.628 52.54,46.08 52.54,45.07 52.782,44.828 U202.6@53.638,44.828 54.38,44.828 54.48,44.928 C214.1@55.405,44.928 55.185,44.708 55.185,43.528 C215.1@55.835,43.528
NetC222_1: C222.1 Q205.1 R236.1 R244.2 | length 5
  Bottom Layer w0.3: R244.2@37.717,135.257 37.717,139.068 Q205.1@38.552,139.902
NetC223_1: C223.1 J202.15 R235.2 | length 99.2
  Signal Layer 4 w0.3: v1(10.68,80.06) 10.68,66.74 11.682,65.738 68.262,65.738 69.51,64.49 69.51,44.562 ; v1(68.8,42.72) 69.51,43.43 69.51,44.562
  Bottom Layer w0.3: C223.1@11.75,78.709 11.021,78.709 10.68,79.05 v1(10.68,80.06) 10.68,80.626 11.184,81.13 R235.2@11.75,81.13
NetC224_1: C224.1 Q205.3 R239.2 R246.2 | length 10.8
  Bottom Layer w0.3: R239.2@35.1,143.707 36.44,143.707 36.44,143.105 37.242,142.302 Q205.3@37.602,142.302 ; C224.1@36.47,143.707 36.47,144.21 36.79,144.53 39.035,144.53 40.59,142.975 R246.2@40.59,141.011
NetC225_1: C225.1 J202.21 R237.2 | length 76.7
  Bottom Layer w0.3: C225.1@32.05,78.71 R237.2@32.05,80.94 32.05,84.97 33.098,86.018 33.702,86.018 38.834,86.018 52.457,72.396 52.457,66.95 52.51,66.897 52.51,66.74 53.75,65.5 54.642,64.608 54.642,57.708 55.114,57.236 58.08,57.236 58.329,56.987 58.333,56.987 58.507,56.813 58.507,56.809 58.608,56.708 58.608,55.012 60.049,53.57 60.049,43.834 61.4,42.484 66.251,42.484 v1(68.887,45.119)
NetC226_1: C226.1 J202.18 R238.1 | length 47.5
  Bottom Layer w0.3: R238.1@52.988,80.041 52.646,80.041 51.91,79.305 C226.1@51.91,78.58 53.351,77.139 53.351,75.553 53.351,67.574 53.351,67.321 54.457,66.215 54.71,66.215 55.045,66.215 58.259,66.215 59.597,64.877 59.597,61.549 59.503,61.454 59.503,59.826 59.503,55.382 61.03,53.855 63.515,53.855 63.823,53.548 63.823,44.243 63.11,43.53 v1(61.76,43.53)
NetC227_1: C227.1 J202.26 R240.1 | length 138.7
  Signal Layer 5 w0.3: v1(32.254,131.85) 32.254,134.423 33.702,135.87 50.08,135.87 52.187,133.763 58.232,133.763 61.613,130.383 61.613,128.611 61.035,128.034 61.035,127.21 61.035,123.483 63.309,121.21 63.309,100.822 67.653,96.479 67.653,94.2 66.758,93.306 66.758,91.408 66.758,69.032 67.12,68.669 67.67,68.119 67.67,50.567 63.823,46.72 v1(61.67,46.72)
  Bottom Layer w0.3: C227.1@32.254,120.703 32.254,122.724 ; v1(32.254,131.85) 32.254,122.724 ; R240.1@33.742,123.103 32.633,123.103 32.254,122.724
NetC228_1: C228.1 J202.30 R242.1 | length 152.8
  Signal Layer 5 w0.3: v1(11.775,131.85) 26.69,131.85 27.237,131.303 32.027,131.303 32.481,131.303 35.113,131.303 38.78,134.97 50.347,134.97 52.001,133.316 56.191,133.316 60.48,129.027 60.48,119.152 62.5,117.132 62.5,109.93 61.89,109.32 61.89,107.54 62.861,106.569 62.861,100.844 62.861,100.637 67.205,96.293 67.205,94.386 66.758,93.938 66.311,93.491 66.311,68.846 66.758,68.399 67.223,67.934 67.223,51.193 64.35,48.32 v1(61.67,48.32)
  Bottom Layer w0.3: C228.1@11.775,121.366 11.775,122.425 ; v1(11.775,131.85) 11.775,122.425 ; R242.1@12.3,122.95 11.775,122.425
NetC229_1: C229.1 J202.25 R243.2 | length 124.5
  Signal Layer 1 w0.3: v1(52.127,131.85) 66.906,131.85 68.294,133.238 70.206,133.238 72.26,131.184 72.26,117.586 71.859,117.185 71.859,104.852 69.411,102.404 69.411,99.992 71.565,97.837 71.815,97.837 71.815,97.388 71.859,97.345 71.859,66.987 71.853,66.987 71.533,66.667 71.533,66.213 71.533,63.195 72.246,62.481 72.573,62.481 72.573,46.72 v1(68.86,46.72)
  Bottom Layer w0.3: v1(52.127,131.85) 52.127,123.498 R243.2@52.805,122.82 52.345,122.36 C229.1@52.345,120.703
NetC235_2: C235.2 R271.1 U204.5 | length 3.7
  Top Layer w0.3: C235.2@46.34,27.414 R271.1@46.34,28.709 46.696,28.709 47.836,29.849 U204.5@48.315,29.849
NetC236_2: C236.2 R270.1 U204.3 | length 3.6
  Top Layer w0.3: U204.3@53.765,28.579 57.14,28.579 R270.1@57.27,28.709
NetC400_2: C400.2 Q400.3 R400.1 R401.2 | length 3.9
  Bottom Layer w0.3: 70.405,53.855 R400.1@70.405,52.865 R401.2@72.087,52.865 ; Q400.3@70.405,54.055 70.555,54.205 C400.2@71.574,54.205
NetC401_2: C401.2 Q401.3 R402.1 R403.2 | length 5.6
  Bottom Layer w0.3: Q401.3@66.735,55.205 66.83,55.3 C401.2@66.83,56.505 66.83,57.52 R403.2@67.02,57.71 66.94,57.79 R402.1@66.94,60.64
NetC402_2: C402.2 Q402.3 R404.1 R405.2 | length 6
  Bottom Layer w0.3: Q402.3@62.165,55.347 62.17,55.352 C402.2@62.17,56.608 62.77,56.608 R405.2@62.77,57.72 62.84,57.79 R404.1@62.84,60.7
NetC403_2: C403.2 R406.1 U400.1 | length 3.5
  Top Layer w0.254: R406.1@1.58,12.82 2.55,12.82 C403.2@2.99,13.26 2.455,13.795 U400.1@2.455,14.96
NetC405_1: C405.1 R407.2 U400.3 | length 3.7
  Top Layer w0.254: C405.1@5.796,14.631 C405.1@5.92,14.756
  Top Layer w0.5: U400.3@4.355,14.96 5.115,15.72 5.92,15.72 ; C405.1@5.92,14.756 5.92,15.72 ; R407.2@5.92,16.37 5.92,15.72
NetD200_2: D200.2 U201.1 | length 1.7
  Bottom Layer w0.3: D200.2@68.974,17.895 69.239,18.16 U201.1@69.239,19.475
NetJ200_1: J200.1 R218.1 | length 4.3
  Top Layer w0.3: J200.1@15.647,136.406 15.647,135.923 v1(16.016,135.554)
  Bottom Layer w0.3: v1@16.01,135.565 R218.1@18.346,137.901
NetJ200_3: J200.3 R223.1 | length 5.9
  Top Layer w0.3: v1(13.194,135.554) 13.647,135.554 J200.3@13.647,136.406
  Bottom Layer w0.3: R223.1@9.891,137.955 9.891,137.449 11.775,135.565 v1@13.189,135.565
NetJ201_1: J201.1 R231.1 | length 4
  Top Layer w0.3: v1(27.29,135.62) J201.1@27.29,136.455
  Bottom Layer w0.3: v1(27.29,135.62) 27.366,135.544 28.084,135.544 R231.1@29.738,137.198
NetJ201_3: J201.3 R234.1 | length 5.6
  Top Layer w0.3: J201.3@25.288,136.477 25.3,136.465 v1(25.3,135.63)
  Bottom Layer w0.3: R234.1@21.148,137.008 22.526,135.63 v1(25.3,135.63)
NetJ400_2: J400.2 R459.2 | length 5.9
  Top Layer w0.3: J400.2@58.23,136.13 58.23,136.757 58.63,137.157 v1(58.63,137.53)
  Bottom Layer w0.3: R459.2@55.918,139.89 55.918,139.082 56.72,138.28 58.22,138.28 58.63,137.87 v1(58.63,137.53)
NetQ200_1: Q200.1 R207.2 | length 1.2
  Bottom Layer w0.3: R207.2@69.481,25.255 69.729,25.502 69.729,26.365
NetQ200_2: Q200.2 R202.1 | length 1.4
  Bottom Layer w0.3: R202.1@68.394,26.775 68.569,26.95 Q200.2@69.729,26.95
NetQ201_3: Q201.3 R223.2 | length 3.5
  Bottom Layer w0.3: R223.2@9.891,139.155 12.245,136.801 Q201.3@12.397,136.801
NetQ202_2: Q202.2 R218.2 | length 1.6
  Bottom Layer w0.3: Q202.2@16.85,139.255 18.193,139.255 R218.2@18.346,139.101
NetQ203_3: Q203.3 R234.2 | length 3.2
  Bottom Layer w0.3: R234.2@21.148,138.208 22.458,138.208 Q203.3@23.813,136.853
NetQ204_2: Q204.2 R231.2 | length 3.1
  Bottom Layer w0.3: v1@28.46,140.49 28.448,140.478 Q204.2@28.448,139.308 29.278,139.308 29.738,138.848 R231.2@29.738,138.398
  other v1: 28.466,140.479
NetQ207_1: Q207.1 R245.1 R247.2 | length 4.4
  Bottom Layer w0.3: R247.2@34.817,133.295 34.817,132.812 35.007,132.622 36.189,132.622 36.485,132.917 36.485,133.203 36.485,133.345 37.47,134.33 R245.1@37.732,134.33
NetQ207_3: Q207.3 R244.1 | length 1
  Bottom Layer w0.3: 36.262,134.322 36.262,135.002 R244.1@36.517,135.257
NetR205_1: R205.1 U200.5 | length 2.1
  Top Layer w0.406: U200.5@48.578,39.768 48.578,40.019 49.591,41.032 R205.1@49.891,40.732
NetR212_1: R212.1 U202.5 | length 2.5
  Bottom Layer w0.3: U202.5@53.638,45.478 53.638,45.92 54.246,46.528 R212.1@55.405,46.528
NetR214_1: R214.1 U201.6 | length 1.5
  Bottom Layer w0.3: U201.6@67.939,23.875 68.046,23.982 R214.1@68.046,25.335
NetR215_1: R215.1 U201.5 U201.7 | length 4.9
  Bottom Layer w0.3: R215.1@65.804,23.875 U201.5@67.289,23.875 67.289,23.031 67.65,22.67 68.445,22.67 68.589,22.814 U201.7@68.589,23.875
NetR220_1: R220.1 R224.2 | length 1.6
  Bottom Layer w0.3: R224.2@56.558,38.82 56.558,40.383 R220.1@56.57,40.395
NetR221_1: R221.1 R225.2 | length 1.6
  Top Layer w0.3: R221.1@41.49,33.797 43.073,33.797 R225.2@43.08,33.79
NetR222_1: R222.1 R226.2 | length 1.7
  Top Layer w0.3: R222.1@35.643,22.111 R226.2@37.322,22.111
NetR232_2: R232.2 U204.1 U204.2 | length 3.2
  Top Layer w0.3: U204.1@53.765,26.039 U204.2@53.765,27.309 53.9,27.444 R232.2@55.636,27.444
NetR233_2: R233.2 U204.6 U204.7 | length 6.4
  Top Layer w0.3: U204.7@48.315,27.309 48.315,27.944 ; U204.6@48.315,28.579 48.315,27.944 ; R233.2@49.29,31.694 49.891,31.092 49.891,28.744 49.092,27.944 48.315,27.944
NetR428_1: R428.1 U402.7 | length 2.1
  Bottom Layer w0.3: R428.1@64.508,74.395 65.035,74.922 U402.7@65.035,76.227
NetR435_1: R435.1 U402.3 | length 1.6
  Bottom Layer w0.3: R435.1@66.082,82.895 66.305,82.672 U402.3@66.305,81.37
ORING_GATE: Q403.9 U400.5 | length 6.3
  Top Layer w0.254: Q403.9@2.71,23.23 2.36,23.23 2.36,18.969 3.405,17.924 U400.5@3.405,17.71
PSKILL: C409.1 R410.1 R416.2 R420.2 | length 82.2
  Signal Layer 1 w0.3: v4(52.21,4.24) 52.502,4.532 53.157,5.187 53.157,7.848 53.157,9.707 53.157,10.527 53.818,11.187 54.602,11.187 54.62,11.17 55.28,11.83 55.263,11.848 55.263,16.932 60.323,21.993 60.323,63.636 62.5,65.813 62.5,73.332 60.497,75.334 v1(60.497,75.815)
  Bottom Layer w0.3: R416.2@60.3,80.01 60.3,78.396 C409.1@60.214,78.31 60.214,76.993 R420.2@60.497,76.71 v1(60.497,75.815) 60.508,75.805 R410.1@60.508,75.19
PWM1H_SYNC_0C: J202.49 pad.1@17.92,76.31 | length 105.2
  Bottom Layer w0.3: 18.7,76.31 19.21,76.31 20.13,77.23 20.13,79.846 29.437,89.153 30.744,90.46 31.8,90.46 32.743,89.517 32.743,86.786 33.063,86.465 33.517,86.465 39.345,86.465 52.904,72.906 52.904,67.136 54.272,65.768 58.074,65.768 59.055,64.787 59.055,55.197 60.497,53.756 60.497,44.019 61.585,42.931 65.936,42.931 67.88,44.875 67.88,55.33 v1(68.87,56.32)
  other v2: 18.39,76.31
PWM2H_SYNC_60C: J202.53 pad.1@37.72,76.31 | length 47.4
  Signal Layer 2 w0.3: v1(53.36,61.47) 53.36,58.991 55.114,57.236 60.011,57.236 62.322,54.925 65.82,54.925 68.832,57.937 v1(68.901,57.937)
  Bottom Layer w0.3: v2(38.19,76.31) 47.21,76.31 52.009,71.511 52.009,66.765 52.063,66.712 52.063,66.555 53.36,65.257 v1(53.36,61.47)
PWM3H_SYNC_120C: J202.50 pad.1@57.61,76.31 | length 27.8
  Signal Layer 5 w0.3: v2(58.08,76.31) 59.56,76.31 60.218,76.31 60.584,76.676 63.861,76.676 63.946,76.591 64.223,76.591 65.373,75.441 65.373,58.901 63.626,57.155 v1(63.626,56.288)
PWM4H_SYNC_180C: J202.54 pad.1@57.718,118.305 | length 66.9
  Signal Layer 3 w0.3: v2(58.188,118.305) 58.765,118.305 63.453,113.617 63.453,106.387 65.55,104.29 65.55,99.983 63.968,98.401 63.647,98.08 63.26,97.693 63.26,91.387 65.081,89.566 65.081,61.29 v1(61.67,57.879)
PWM5H_SYNC_240C: J202.57 pad.1@37.724,118.303 | length 99.2
  Signal Layer 3 w0.3: pad.1@37.724,118.303 v2(38.194,118.303) 39.418,118.303 50.905,129.79 55.166,129.79 61.788,129.79 66.409,125.169 66.409,64.648 68.324,62.732 v1(68.901,62.732)
PWM6H_SYNC_300C: J202.61 pad.1@17.92,118.31 | length 123.6
  Signal Layer 3 w0.3: v2(18.39,118.31) 21.6,118.31 28.72,125.43 28.72,132.62 59.706,132.62 66.856,125.47 66.856,66.436 68.901,64.392 v1(68.901,64.324)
